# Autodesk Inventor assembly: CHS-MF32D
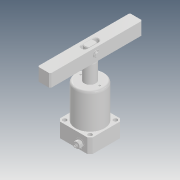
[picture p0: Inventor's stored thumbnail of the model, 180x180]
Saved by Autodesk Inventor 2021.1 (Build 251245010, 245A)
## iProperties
Created: 2020-02
Part Number: CHS-MF32D
Description: STEP AP214
Document SubType Name: Assembly
Designer: user
Title: chs-mf32d_asm.STEP
Revision Number: ÈÎºÎ
Sending System: SolidWorks 2016
Preprocessor: SwSTEP 2.0
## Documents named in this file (10)
- D:\Vault_2016\Projekty\Clamptek\Hydraulic\CHS\CHS-32\Inventor\CHS-MF32D\CHS-MF32D.iam
- D:\Vault_2016\Projekty\Clamptek\Hydraulic\CHS\CHS-32\Inventor\CHS-MF32D\CHS-32D-02_5.ipt
- D:\Vault_2016\Projekty\Clamptek\Hydraulic\CHS\CHS-32\Inventor\CHS-MF32D\CHS-TXF-01.ipt
- D:\Vault_2016\Projekty\Clamptek\Hydraulic\CHS\CHS-32\Inventor\CHS-MF32D\CHS-MF32-TXF-02.ipt
- D:\Vault_2016\Projekty\Clamptek\Hydraulic\CHS\CHS-32\Inventor\CHS-MF32D\CHS-MF32-TXF-03.ipt
- D:\Vault_2016\Projekty\Clamptek\Hydraulic\CHS\CHS-32\Inventor\CHS-MF32D\M6.ipt
- D:\Vault_2016\Projekty\Clamptek\Hydraulic\CHS\CHS-32\Inventor\CHS-MF32D\CHS-32D-01_6.ipt
- D:\Vault_2016\Projekty\Clamptek\Hydraulic\CHS\CHS-32\Inventor\CHS-MF32D\CHS-MF32BT.ipt
- D:\Vault_2016\Projekty\Clamptek\Hydraulic\CHS\CHS-32\Inventor\CHS-MF32D\Öá8µ²È¦.ipt
- D:\Vault_2016\Projekty\Clamptek\Hydraulic\CHS\CHS-32\Inventor\CHS-MF32D\Xiaozhou.ipt
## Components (10 placed, 10 different names)
1. CHS-32D-02_5_1
2. CHS-TXF-01_2
3. CHS-MF32-TXF-02_3
4. CHS-MF32-TXF-03_4
5. M6_5
6. CHS-32D-01_6_6
7. CHS-MF32BT_7
8. Öá8µ²È¦_8
9. Xiaozhou_9
10. Öá8µ²È¦_10
